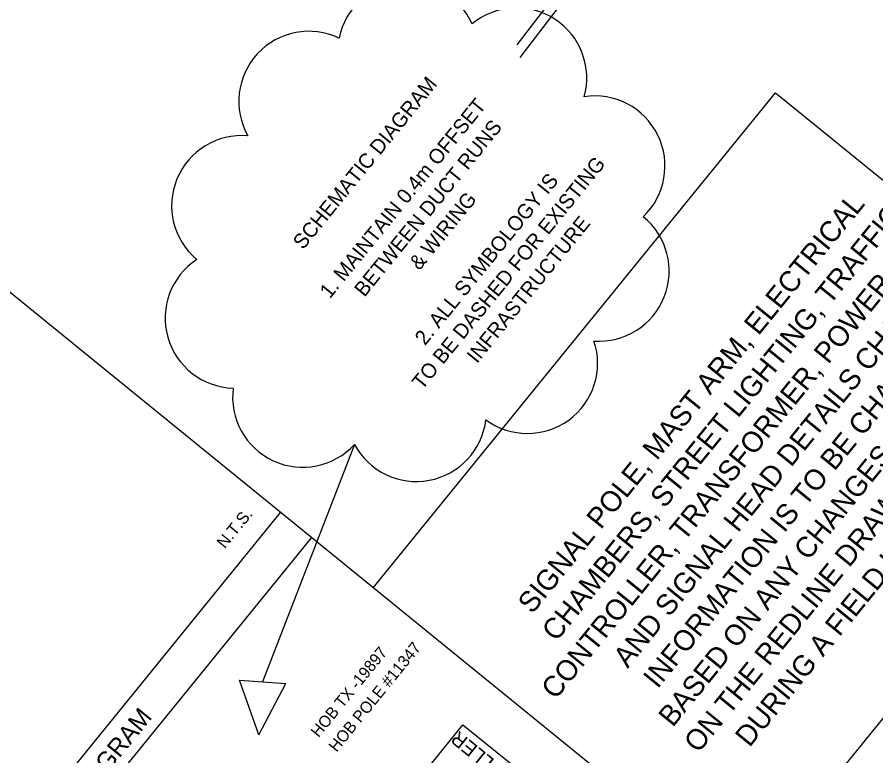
# Model space of a CAD drawing. Extents: x 592613 to 600223, y 4837996 to 4840103.
# Drawn here: x 592734.31 to 592777.46, y 4838942.52 to 4838979.64 of the extents above; entities that cross this region are included whole.
import ezdxf

# ---------------------------------------------------------------- set-up
doc = ezdxf.new("R2010")
doc.units = 0
for name, color, linetype in [('ENG_BORDER', 7, 'Continuous'), ('ENG_CURB-BACK', 7, 'Continuous'), ('ENG_LIMITS', 7, 'Continuous'), ('ENG_TITLEBLOCK', 7, 'Continuous'), ('ENG_TX_TITLEBLOCK', 7, 'Continuous'), ('Level 12', 7, 'Continuous'), ('Level 43', 7, 'Continuous'), ('ROW_ENG_ROW BO', 7, 'Continuous'), ('TCS_CONTROLLER', 7, 'Continuous'), ('TCS_HYDROSUPPLY', 7, 'Continuous')]:
    doc.layers.add(name, color=color, linetype=linetype)

msp = doc.modelspace()

# ---------------------------------------------------------------- linework, layer by layer
at = {"layer": 'ENG_BORDER'}
msp.add_line((592790.401, 4838919.927), (592686.018, 4839004.737), dxfattribs=at)
at = {"layer": 'ENG_CURB-BACK'}
msp.add_line((592759.442, 4838978.253), (592768.704, 4838990.383), dxfattribs=at)
at = {"layer": 'ENG_LIMITS'}
for p, q in [((592751.259, 4838958.169), (592746.641, 4838946.238)), ((592746.452, 4838943.571), (592745.479, 4838946.321)), ((592745.479, 4838946.321), (592747.803, 4838946.156)), ((592746.452, 4838943.571), (592747.803, 4838946.156))]:
    msp.add_line(p, q, dxfattribs=at)
for centre, radius, start, end in [((592753.939, 4838977.886), 3.522, 23.5797, 168.5797), ((592759.41, 4838976.578), 3.523, 344.5454, 129.5454), ((592748.967, 4838975.405), 3.523, 64.4605, 209.4605), ((592763.339, 4838972.157), 3.523, 313.7009, 98.7009), ((592745.595, 4838970.162), 3.524, 85.0327, 230.0327), ((592763.549, 4838966.878), 3.523, 265.8513, 50.8513), ((592745.267, 4838964.519), 3.522, 123.3328, 268.3328), ((592759.954, 4838962.242), 3.523, 233.5855, 18.5855), ((592748.658, 4838960.544), 3.523, 172.595, 317.595), ((592754.366, 4838959.829), 3.523, 208.1174, 353.1174)]:
    msp.add_arc(centre, radius, start, end, dxfattribs=at)
at = {"layer": 'ENG_TITLEBLOCK'}
for p, q in [((592770.854, 4838935.809), (592843.567, 4839025.495)), ((592752.204, 4838950.962), (592772.414, 4838975.832)), ((592791.029, 4838960.693), (592772.408, 4838975.825)), ((592720.007, 4838920.852), (592747.546, 4838954.746)), ((592721.564, 4838919.587), (592749.103, 4838953.481))]:
    msp.add_line(p, q, dxfattribs=at)
at = {"layer": 'ROW_ENG_ROW BO'}
msp.add_line((592766.831, 4838987.113), (592759.571, 4838977.605), dxfattribs=at)
at = {"layer": 'TCS_CONTROLLER'}
msp.add_lwpolyline([(592756.709, 4838944.087), (592762.404, 4838939.488), (592759.147, 4838935.456), (592753.453, 4838940.055)], close=True, dxfattribs=at)

# ---------------------------------------------------------------- texts
at = {"layer": 'ENG_TX_TITLEBLOCK'}
for s, height, p in [('SCHEMATIC DIAGRAM ', 0.74209, (592748.675, 4838967.918)), ('1. MAINTAIN 0.4m OFFSET ', 0.74209, (592750.021, 4838965.455)), ('BETWEEN DUCT RUNS', 0.74209, (592751.76, 4838965.537)), ('TO BE DASHED FOR EXISTING ', 0.74209, (592754.661, 4838960.869)), ('2. ALL SYMBOLOGY IS', 0.74209, (592754.803, 4838963.104)), ('CONTROLLER, TRANSFORMER, POWER SUPPLY, ', 1.03687, (592761.365, 4838945.304)), ('& WIRING ', 0.7421, (592754.523, 4838966.878)), ('SIGNAL POLE, MAST ARM, ELECTRICAL ', 1.03687, (592760.188, 4838949.609)), ('CHAMBERS, STREET LIGHTING, TRAFFIC ', 1.03687, (592761.396, 4838948.218)), ('INFRASTRUCTURE', 0.74209, (592757.415, 4838962.199)), ('AND SIGNAL HEAD DETAILS CHART ', 1.03687, (592764.988, 4838946.884)), ('INFORMATION IS TO BE CHANGED ', 1.03687, (592766.49, 4838945.855)), ('BASED ON ANY CHANGES INDICATED ', 1.03687, (592767.255, 4838943.919)), ('ON THE REDLINE DRAWINGS AND/ OR', 1.03687, (592768.536, 4838942.618)), (' DURING A FIELD INVESTIGATION.', 1.03687, (592770.867, 4838942.61))]:
    msp.add_text(s, height=height, rotation=50.9012, dxfattribs=at).set_placement(p)
at = {"layer": 'Level 12'}
msp.add_text('N.T.S.', height=0.6, rotation=50.9062, dxfattribs=at).set_placement((592744.749, 4838952.897))
at = {"layer": 'Level 43'}
msp.add_text('SCHEMATIC WIRING DIAGRAM', height=0.9, rotation=50.9062, dxfattribs=at).set_placement((592729.874, 4838930.598))
at = {"layer": 'TCS_CONTROLLER'}
msp.add_text('CONTROLLER', height=0.7125, rotation=141.0744, dxfattribs=at).set_placement((592761.543, 4838939.719))
at = {"layer": 'TCS_HYDROSUPPLY'}
for s, p in [('HOB TX -19897', (592749.458, 4838943.405)), ('HOB POLE #11347', (592750.36, 4838942.671))]:
    msp.add_text(s, height=0.5814, rotation=50.881, dxfattribs=at).set_placement(p)

doc.saveas('drawing.dxf')
